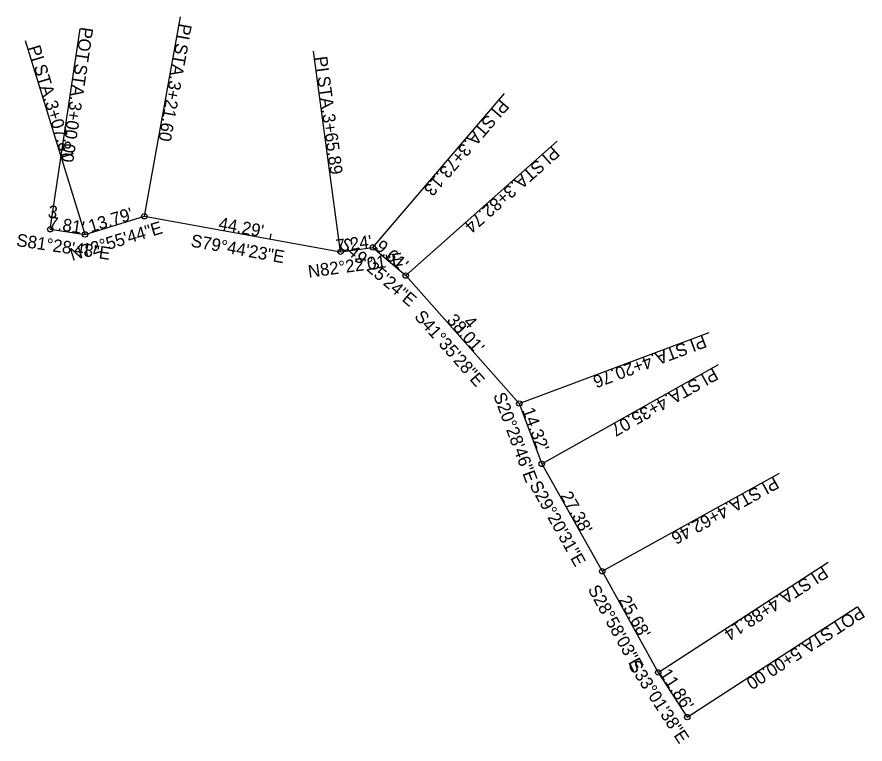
# Model space of a CAD drawing. Extents: x 2347439 to 2347627, y 247845 to 248007.
import ezdxf

# ---------------------------------------------------------------- set-up
doc = ezdxf.new("R2010")
doc.units = 0
for name, color, linetype in [('GE_P_Alignment', 7, 'Continuous'), ('GE_P_Alignment_100_Bearings', 7, 'Continuous'), ('GE_P_Alignment_100_Cardinal_Points', 7, 'Continuous'), ('GE_P_Alignment_100_Distances', 7, 'Continuous'), ('GE_P_Alignment_100_Stations', 7, 'Continuous')]:
    doc.layers.add(name, color=color, linetype=linetype)

msp = doc.modelspace()

# ---------------------------------------------------------------- linework, layer by layer
at = {"layer": 'GE_P_Alignment'}
for p, q in [((2347453.88, 247958.62), (2347467.06, 247962.67)), ((2347467.06, 247962.67), (2347510.64, 247954.78)), ((2347446.15, 247959.78), (2347453.88, 247958.62)), ((2347510.64, 247954.78), (2347517.82, 247955.74)), ((2347517.82, 247955.74), (2347525.12, 247949.49)), ((2347525.12, 247949.49), (2347550.35, 247921.06)), ((2347525.12, 247949.49), (2347550.35, 247921.06)), ((2347550.35, 247921.06), (2347555.36, 247907.65)), ((2347555.36, 247907.65), (2347568.78, 247883.78)), ((2347568.78, 247883.78), (2347581.22, 247861.31)), ((2347581.22, 247861.31), (2347587.68, 247851.37))]:
    msp.add_line(p, q, dxfattribs=at)
at = {"layer": 'GE_P_Alignment_100_Cardinal_Points'}
for p, q in [((2347467.06, 247962.67), (2347475.08, 248006.95)), ((2347446.15, 247959.78), (2347452.82, 248004.28)), ((2347453.88, 247958.62), (2347440.67, 248001.64)), ((2347510.64, 247954.78), (2347504.66, 247999.38)), ((2347517.82, 247955.74), (2347547.09, 247989.92)), ((2347525.12, 247949.49), (2347558.77, 247979.36)), ((2347550.35, 247921.06), (2347592.51, 247936.81)), ((2347555.36, 247907.65), (2347594.59, 247929.7)), ((2347568.78, 247883.78), (2347608.15, 247905.57)), ((2347581.22, 247861.31), (2347618.95, 247885.84)), ((2347587.68, 247851.37), (2347625.41, 247875.89))]:
    msp.add_line(p, q, dxfattribs=at)
for centre in [(2347467.06, 247962.67), (2347446.15, 247959.78), (2347453.88, 247958.62), (2347510.64, 247954.78), (2347517.82, 247955.74), (2347525.12, 247949.49), (2347550.35, 247921.06), (2347555.36, 247907.65), (2347568.78, 247883.78), (2347581.22, 247861.31), (2347587.68, 247851.37)]:
    msp.add_circle(centre, 0.6, dxfattribs=at)
at = {"layer": 'GE_P_Alignment_100_Stations'}
for p, q in [((2347446.15, 247959.78), (2347446.45, 247961.76)), ((2347495.01, 247957.61), (2347495.22, 247958.79)), ((2347536.57, 247936.59), (2347538.07, 247937.91)), ((2347562.68, 247894.64), (2347563.72, 247895.23))]:
    msp.add_line(p, q, dxfattribs=at)

# ---------------------------------------------------------------- texts
at = {"layer": 'GE_P_Alignment_100_Bearings'}
for s, rotation, p in [('N72°55\'44"E', 17.0711, (2347451.02, 247952.72)), ('S81°28\'48"E', 351.4801, (2347438.49, 247956.07)), ('S79°44\'23"E', 349.7398, (2347477.23, 247955.95)), ('S49°25\'24"E', 319.4233, (2347510.04, 247956.09)), ('N82°22\'01"E', 7.6331, (2347503.6, 247949)), ('S41°35\'28"E', 311.5911, (2347526.88, 247940.27)), ('S20°28\'46"E', 290.4794, (2347544.53, 247922.92)), ('S29°20\'31"E', 299.342, (2347552.53, 247902.9)), ('S28°58\'03"E', 298.9675, (2347565.5, 247879.79)), ('S33°01\'38"E', 303.0273, (2347574.46, 247862.89))]:
    msp.add_text(s, height=2.8, rotation=rotation, dxfattribs=at).set_placement(p)
at = {"layer": 'GE_P_Alignment_100_Cardinal_Points'}
for s, rotation, p in [('POT', 261.4801, (2347452.95, 248004.83)), ('PI', 259.7398, (2347474.88, 248005.62)), ('PI', 287.0711, (2347441.16, 248000.18)), (' STA. ', 259.7398, (2347474.27, 248002.29)), (' STA. ', 287.0711, (2347442.15, 247996.94)), (' STA. ', 261.4801, (2347451.88, 247997.71)), ('PI', 277.6331, (2347504.89, 247998.03)), ('3+21.60', 259.7398, (2347472.59, 247992.99)), (' STA. ', 277.6331, (2347505.34, 247994.67)), ('3+07.81', 287.0711, (2347444.93, 247987.91)), ('3+00.00', 261.4801, (2347450.48, 247988.37)), ('PI', 229.4233, (2347546.2, 247988.82)), ('3+65.89', 277.6331, (2347506.59, 247985.3)), (' STA. ', 229.4233, (2347543.99, 247986.24)), ('3+73.13', 229.4233, (2347537.85, 247979.07)), ('PI', 221.5911, (2347557.74, 247978.39)), (' STA. ', 221.5911, (2347555.21, 247976.14)), ('3+82.74', 221.5911, (2347548.14, 247969.87)), ('PI', 200.4794, (2347591.28, 247936.3)), (' STA. ', 200.4794, (2347588.1, 247935.11)), ('4+20.76', 200.4794, (2347579.25, 247931.81)), ('PI', 209.342, (2347593.5, 247929.04)), (' STA. ', 209.342, (2347590.55, 247927.38)), ('4+35.07', 209.342, (2347582.31, 247922.75)), ('PI', 208.9675, (2347607.01, 247904.89)), (' STA. ', 208.9675, (2347604.04, 247903.25)), ('4+62.46', 208.9675, (2347595.77, 247898.67)), ('PI', 213.0273, (2347617.78, 247885.03)), (' STA. ', 213.0273, (2347614.94, 247883.18)), ('4+88.14', 213.0273, (2347607.01, 247878.03)), ('POT', 213.0273, (2347625.91, 247876.16)), (' STA. ', 213.0273, (2347619.87, 247872.24)), ('5+00.00', 213.0273, (2347611.95, 247867.09))]:
    msp.add_text(s, height=2.8, rotation=rotation, dxfattribs=at).set_placement(p)
at = {"layer": 'GE_P_Alignment_100_Distances'}
for s, rotation, p in [("13.79'", 17.0711, (2347455.14, 247959.05)), ("7.81'", 351.4801, (2347445.63, 247959.9)), ("44.29'", 349.7398, (2347483.38, 247959.76)), ("7.24'", 7.6331, (2347509.82, 247954.69)), ("9.61'", 319.4233, (2347518.12, 247955.54)), ("38.01'", 311.5911, (2347534.08, 247939.46)), ("14.32'", 290.4794, (2347550.95, 247919.58)), ("27.38'", 299.342, (2347559.38, 247900.58)), ("25.68'", 298.9675, (2347572.34, 247877.43)), ("11.86'", 303.0273, (2347581.45, 247861.02))]:
    msp.add_text(s, height=2.8, rotation=rotation, dxfattribs=at).set_placement(p)
at = {"layer": 'GE_P_Alignment_100_Stations'}
for s, rotation, p in [('3', 351.4801, (2347445.5, 247962.41)), ('4', 311.5911, (2347537.76, 247939.02))]:
    msp.add_text(s, height=2.8, rotation=rotation, dxfattribs=at).set_placement(p)

doc.saveas('drawing.dxf')
